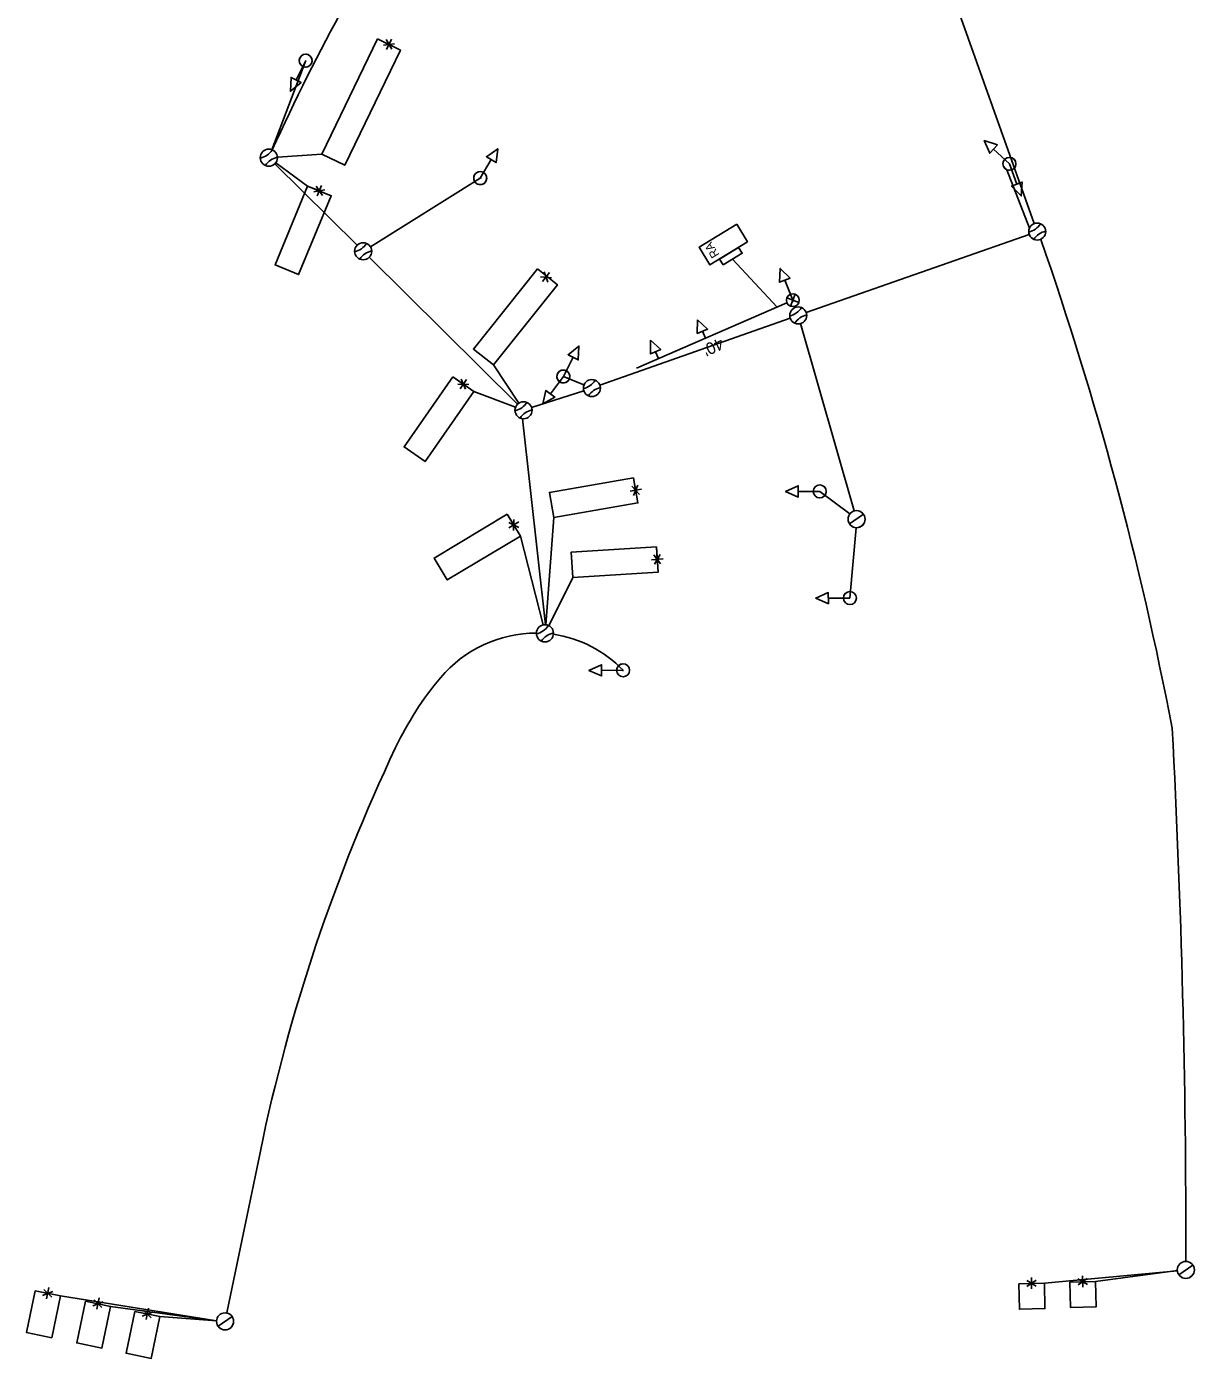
# Model space of a CAD drawing. Extents: x 596176 to 605330, y 332416 to 402398.
# Drawn here: x 602306.3 to 602580, y 356809.5 to 357121.7 of the extents above; entities that cross this region are included whole.
import ezdxf

# ---------------------------------------------------------------- set-up
doc = ezdxf.new("R2010")
doc.units = 0
for name, color, linetype in [('P_LTG', 7, 'Continuous'), ('P_SIG', 7, 'Continuous'), ('P_SIG_Bold', 7, 'Continuous'), ('P_SIG_Conduit', 7, 'Continuous'), ('P_SIG_Loops', 7, 'Continuous')]:
    doc.layers.add(name, color=color, linetype=linetype)

# ---------------------------------------------------------------- blocks, each defined once
blk = doc.blocks.new('_U319')
at = {"layer": 'P_SIG'}
for p, q in [((-0.68, 0.11), (-0.74, 0.13)), ((-0.72, 0.06), (-0.74, 0.13)), ((-0.02, -0.02), (-0.44, -0.02))]:
    blk.add_line(p, q, dxfattribs=at)
for centre, radius, start, end in [((-0.48, 0.45), 0.392, 205.2667, 239.91514), ((-0.38, 0.36), 0.462, 189.31535, 221.17149), ((-0.41, 0.42), 0.442, 221.4708, 266.03474)]:
    blk.add_arc(centre, radius, start, end, dxfattribs=at)

msp = doc.modelspace()

# ---------------------------------------------------------------- linework, layer by layer
at = {"layer": 'P_SIG'}
for p, q in [((602369.5, 357109.17), (602371.75, 357113.7)), ((602532.98, 357092.96), (602536.69, 357089.52)), ((602415.26, 357090.49), (602412.65, 357086.16)), ((602538.45, 357084.77), (602536.7, 357089.51)), ((602482.25, 357055.94), (602471.82, 357067.19)), ((602484.06, 357062.24), (602485.93, 357057.54)), ((602464.75, 357050.26), (602465.45, 357048.63)), ((602453.75, 357045.47), (602454.45, 357043.84)), ((602434.45, 357044.16), (602432.14, 357039.66)), ((602429.11, 357035.61), (602432.14, 357039.66)), ((602487.18, 357012.73), (602492.24, 357012.73)), ((602499.21, 357005.09), (602502.51, 357007.35)), ((602494.26, 356987.71), (602499.31, 356987.71)), ((602441.1, 356970.78), (602446.15, 356970.79)), ((602576.39, 356829.12), (602579.69, 356831.38)), ((602351.2, 356817.05), (602354.5, 356819.31))]:
    msp.add_line(p, q, dxfattribs=at)
for points in [[(602368.19, 357106.51), (602368.32, 357109.75), (602370.69, 357108.58), (602368.19, 357106.51)], [(602368.32, 357109.75), (602368.19, 357106.51), (602370.69, 357108.58), (602368.32, 357109.75)], [(602530.8, 357094.97), (602533.87, 357093.93), (602532.08, 357091.99), (602530.8, 357094.97)], [(602530.8, 357094.97), (602533.87, 357093.93), (602532.08, 357091.99), (602530.8, 357094.97)], [(602533.87, 357093.93), (602530.8, 357094.97), (602532.08, 357091.99), (602533.87, 357093.93)], [(602416.78, 357093.03), (602416.39, 357089.82), (602414.13, 357091.17), (602416.78, 357093.03)], [(602416.39, 357089.82), (602416.78, 357093.03), (602414.13, 357091.17), (602416.39, 357089.82)], [(602539.48, 357081.99), (602537.22, 357084.31), (602539.69, 357085.23), (602539.48, 357081.99)], [(602537.22, 357084.31), (602539.48, 357081.99), (602539.69, 357085.23), (602537.22, 357084.31)], [(602482.97, 357064.99), (602485.29, 357062.73), (602482.84, 357061.75), (602482.97, 357064.99)], [(602482.97, 357064.99), (602485.29, 357062.73), (602482.84, 357061.75), (602482.97, 357064.99)], [(602485.29, 357062.73), (602482.97, 357064.99), (602482.84, 357061.75), (602485.29, 357062.73)], [(602435.79, 357046.8), (602435.62, 357043.56), (602433.27, 357044.76), (602435.79, 357046.8)], [(602435.62, 357043.56), (602435.79, 357046.8), (602433.27, 357044.76), (602435.62, 357043.56)], [(602427.35, 357033.23), (602428.06, 357036.39), (602430.17, 357034.82), (602427.35, 357033.23)], [(602428.06, 357036.39), (602427.35, 357033.23), (602430.17, 357034.82), (602428.06, 357036.39)], [(602484.22, 357012.72), (602487.18, 357014.04), (602487.19, 357011.41), (602484.22, 357012.72)], [(602487.18, 357014.04), (602484.22, 357012.72), (602487.19, 357011.41), (602487.18, 357014.04)], [(602502.51, 357007.35), (602499.21, 357005.09)], [(602491.3, 356987.7), (602494.25, 356989.02), (602494.26, 356986.39), (602491.3, 356987.7)], [(602494.25, 356989.02), (602491.3, 356987.7), (602494.26, 356986.39), (602494.25, 356989.02)], [(602438.14, 356970.77), (602441.09, 356972.1), (602441.1, 356969.46), (602438.14, 356970.77)], [(602441.09, 356972.1), (602438.14, 356970.77), (602441.1, 356969.46), (602441.09, 356972.1)], [(602579.69, 356831.38), (602576.39, 356829.12)], [(602354.5, 356819.31), (602351.2, 356817.05)]]:
    msp.add_lwpolyline(points, dxfattribs=at)
for points in [[(602472.78, 357075.35), (602463.96, 357069.94), (602466.48, 357065.83), (602475.3, 357071.24)], [(602469.57, 357065.81), (602468.73, 357067.17), (602473.23, 357069.93), (602474.07, 357068.56)], [(602463.58, 357052.97), (602465.96, 357050.78), (602463.54, 357049.74)], [(602452.57, 357048.18), (602454.96, 357045.99), (602452.54, 357044.94)]]:
    msp.add_lwpolyline(points, close=True, dxfattribs=at)
for centre, radius in [((602371.75, 357113.7), 1.52), ((602371.75, 357113.7), 1.52), ((602371.75, 357113.7), 1.52), ((602363.11, 357090.95), 2), ((602536.7, 357089.51), 1.52), ((602536.7, 357089.51), 1.52), ((602536.7, 357089.51), 1.52), ((602412.65, 357086.16), 1.52), ((602412.65, 357086.16), 1.52), ((602412.65, 357086.16), 1.52), ((602543.21, 357073.63), 2), ((602385.23, 357069.01), 2), ((602487.2, 357053.97), 2), ((602432.14, 357039.66), 1.52), ((602432.14, 357039.66), 1.52), ((602432.14, 357039.66), 1.52), ((602432.14, 357039.66), 1.52), ((602432.14, 357039.66), 1.52), ((602432.14, 357039.66), 1.52), ((602438.83, 357036.95), 2), ((602422.81, 357031.74), 2), ((602492.24, 357012.73), 1.52), ((602492.24, 357012.73), 1.52), ((602492.24, 357012.73), 1.52), ((602500.86, 357006.22), 2), ((602499.31, 356987.71), 1.52), ((602499.31, 356987.71), 1.52), ((602499.31, 356987.71), 1.52), ((602427.83, 356979.46), 2), ((602446.15, 356970.79), 1.52), ((602446.15, 356970.79), 1.52), ((602446.15, 356970.79), 1.52), ((602578.04, 356830.25), 2), ((602352.85, 356818.18), 2)]:
    msp.add_circle(centre, radius, dxfattribs=at)
for centre, radius, start, end in [((602371.75, 357113.7), 1.52, 63.7061, 243.7061), ((602371.75, 357113.7), 1.52, 243.7061, 63.7061), ((602360.19, 357095.1), 4.36, 282.2572, 328.1103), ((602365.97, 357086.76), 4.36, 101.3562, 147.2093), ((602536.7, 357089.51), 1.52, 110.3847, 290.3847), ((602536.7, 357089.51), 1.52, 290.3847, 110.3847), ((602412.65, 357086.16), 1.52, 59.1253, 239.1253), ((602412.65, 357086.16), 1.52, 239.1253, 59.1253), ((602540.29, 357077.77), 4.36, 282.2572, 328.1103), ((602546.06, 357069.44), 4.36, 101.3562, 147.2093), ((602382.31, 357073.16), 4.36, 282.2572, 328.1103), ((602388.09, 357064.82), 4.36, 101.3562, 147.2093), ((602484.28, 357058.12), 4.36, 282.2572, 328.1103), ((602490.06, 357049.78), 4.36, 101.3562, 147.2093), ((602432.14, 357039.66), 1.52, 53.3587, 233.3587), ((602432.14, 357039.66), 1.52, 63.0248, 243.0248), ((602432.14, 357039.66), 1.52, 233.3587, 53.3587), ((602432.14, 357039.66), 1.52, 243.0248, 63.0248), ((602435.91, 357041.09), 4.36, 282.2572, 328.1103), ((602441.69, 357032.76), 4.36, 101.3562, 147.2093), ((602419.89, 357035.89), 4.36, 282.2572, 328.1103), ((602425.67, 357027.55), 4.36, 101.3562, 147.2093), ((602492.24, 357012.73), 1.52, 0.1787, 180.1787), ((602492.24, 357012.73), 1.52, 180.1787, 0.1787), ((602500.86, 357006.22), 2, 214.3829, 304.6821), ((602500.86, 357006.22), 2, 304.6821, 34.3829), ((602499.31, 356987.71), 1.52, 0.1787, 180.1787), ((602499.31, 356987.71), 1.52, 180.1787, 0.1787), ((602424.91, 356983.6), 4.36, 282.2572, 328.1103), ((602430.69, 356975.27), 4.36, 101.3562, 147.2093), ((602446.15, 356970.79), 1.52, 0.1787, 180.1787), ((602446.15, 356970.79), 1.52, 180.1787, 0.1787), ((602578.04, 356830.25), 2, 304.6821, 34.3829), ((602578.04, 356830.25), 2, 214.3829, 304.6821), ((602352.85, 356818.18), 2, 304.6821, 34.3829), ((602352.85, 356818.18), 2, 214.3829, 304.6821)]:
    msp.add_arc(centre, radius, start, end, dxfattribs=at)
at = {"layer": 'P_SIG_Bold'}
for p, q in [((602484.53, 357058.09), (602487.32, 357056.99)), ((602486.48, 357058.94), (602485.38, 357056.15)), ((602449.25, 357041.58), (602484.55, 357056.94))]:
    msp.add_line(p, q, dxfattribs=at)
msp.add_circle((602485.93, 357057.54), 1.5, dxfattribs=at)
at = {"layer": 'P_SIG_Conduit'}
for p, q in [((602363.83, 357092.82), (602371.75, 357113.7)), ((602364.53, 357089.54), (602383.81, 357070.42)), ((602386.93, 357070.07), (602412.65, 357086.16)), ((602541.39, 357074.46), (602536.06, 357088.14)), ((602386.65, 357067.6), (602421.39, 357033.15)), ((602486.53, 357055.86), (602486.43, 357056.13)), ((602436.98, 357037.7), (602432.14, 357039.66)), ((602499.31, 356987.71), (602500.77, 357004.22))]:
    msp.add_line(p, q, dxfattribs=at)
for points in [[(602524.96, 357124.65), (602542.53, 357075.51)], [(602489.09, 357054.64), (602541.32, 357072.96)], [(602440.72, 357037.61), (602485.31, 357053.31)], [(602500.31, 357008.14), (602487.75, 357052.05)], [(602424.71, 357032.36), (602436.93, 357036.33)], [(602427.94, 356981.46), (602422.53, 357029.76)], [(602499.26, 357007.43), (602492.24, 357012.73)], [(602361.13, 356858.1), (602353.26, 356820.14)]]:
    msp.add_lwpolyline(points, dxfattribs=at)
for centre, radius, start, end in [((602786.9, 356902.02), 464, 151.0197, 155.7252), ((601778.36, 356804.45), 811, 10.85868, 19.24809), ((602425.88, 356950.04), 29.48, 90.0864, 139.8604), ((602425.74, 356951.37), 28.17, 43.5756, 81.6852), ((602461.52, 356920.15), 76, 139.9541, 154.6474), ((600278.02, 356835.81), 2300.03, 359.91139, 3.02617), ((602772.39, 356772.85), 420, 154.6474, 168.2896)]:
    msp.add_arc(centre, radius, start, end, dxfattribs=at)
at = {"layer": 'P_SIG_Loops'}
for p, q in [((602391.27, 357117.5), (602388.57, 357118.8)), ((602389.97, 357117.31), (602392.54, 357117.65)), ((602390.59, 357118.62), (602391.93, 357116.41)), ((602391.85, 357118.74), (602390.68, 357116.33)), ((602364.73, 357089.77), (602372.2, 357084.31)), ((602375.54, 357091.78), (602365.11, 357091.08)), ((602374.97, 357083.17), (602372.2, 357084.31)), ((602373.68, 357082.91), (602376.24, 357083.4)), ((602374.23, 357084.25), (602375.7, 357082.12)), ((602375.48, 357084.44), (602374.46, 357081.97)), ((602428.92, 357064.03), (602427.27, 357061.93)), ((602427.66, 357064.19), (602428.5, 357061.74)), ((602426.78, 357063.04), (602429.37, 357062.82)), ((602415.8, 357042.4), (602421.72, 357033.42)), ((602408.7, 357037.84), (602406.24, 357039.55)), ((602409.47, 357038.97), (602407.94, 357036.78)), ((602408.21, 357039.06), (602409.18, 357036.66)), ((602407.38, 357037.86), (602409.99, 357037.79)), ((602420.94, 357032.45), (602411.16, 357036.12)), ((602448.18, 357013.92), (602449.97, 357012.03)), ((602449.09, 357012.97), (602448.58, 357015.93)), ((602449.61, 357014.19), (602448.6, 357011.8)), ((602450.44, 357013.23), (602447.8, 357012.77)), ((602420.52, 357004.85), (602418.98, 357007.42)), ((602419.33, 357005.4), (602421.68, 357004.28)), ((602421.69, 357005.57), (602419.4, 357004.19)), ((602420.57, 357006.16), (602420.49, 357003.57)), ((602428.02, 356981.45), (602429.9, 357006.59)), ((602427.39, 356981.41), (602422.07, 357002.27)), ((602454.15, 356996.78), (602453.96, 356999.77)), ((602455.52, 356996.88), (602452.84, 356996.72)), ((602453.35, 356997.82), (602454.91, 356995.75)), ((602454.8, 356997.93), (602453.53, 356995.67)), ((602434.38, 356992.53), (602428.73, 356981.25)), ((602544.88, 356827.16), (602576.05, 356830.06)), ((602576.05, 356830.09), (602556.88, 356827.55)), ((602541.88, 356827.08), (602538.88, 356827.01)), ((602540.76, 356827.78), (602542.97, 356826.42)), ((602540.81, 356826.33), (602542.95, 356827.81)), ((602541.83, 356828.46), (602541.9, 356825.78)), ((602553.88, 356827.47), (602550.88, 356827.4)), ((602552.75, 356828.17), (602554.96, 356826.81)), ((602552.8, 356826.71), (602554.94, 356828.2)), ((602553.82, 356828.85), (602553.89, 356826.17)), ((602310.1, 356824.25), (602312.51, 356825.21)), ((602310.38, 356825.68), (602312.22, 356823.86)), ((602311.58, 356826.09), (602311.03, 356823.47)), ((602314.25, 356824.14), (602350.86, 356818.28)), ((602323.33, 356823.66), (602322.79, 356821.03)), ((602321.85, 356821.81), (602324.27, 356822.77)), ((602322.14, 356823.24), (602323.98, 356821.42)), ((602350.86, 356818.28), (602326.01, 356821.7)), ((602333.42, 356819.41), (602335.83, 356820.37)), ((602333.7, 356820.84), (602335.54, 356819.02)), ((602334.9, 356821.25), (602334.35, 356818.63)), ((602350.86, 356818.28), (602337.57, 356819.3))]:
    msp.add_line(p, q, dxfattribs=at)
for points in [[(602388.57, 357118.8), (602375.52, 357091.79), (602380.92, 357089.18), (602393.97, 357116.19)], [(602372.2, 357084.31), (602364.56, 357065.83), (602370.1, 357063.54), (602377.75, 357082.02)], [(602426.05, 357064.86), (602411.08, 357046.1), (602415.8, 357042.4), (602430.77, 357061.15)], [(602406.24, 357039.55), (602394.81, 357023.14), (602399.73, 357019.71), (602411.16, 357036.12)], [(602448.58, 357015.93), (602428.87, 357012.5), (602429.9, 357006.59), (602449.61, 357010.02)], [(602418.98, 357007.42), (602401.84, 356997.11), (602404.93, 356991.97), (602422.07, 357002.27)], [(602453.96, 356999.77), (602434, 356998.52), (602434.38, 356992.53), (602454.34, 356993.79)], [(602538.88, 356827.01), (602539.03, 356821.01), (602545.02, 356821.16), (602544.88, 356827.16)], [(602550.88, 356827.4), (602551.02, 356821.4), (602557.02, 356821.55), (602556.88, 356827.55)], [(602308.38, 356825.35), (602306.35, 356815.56), (602312.22, 356814.34), (602314.25, 356824.14)], [(602320.13, 356822.92), (602318.1, 356813.13), (602323.98, 356811.91), (602326.01, 356821.7)], [(602331.7, 356820.52), (602329.67, 356810.72), (602335.54, 356809.51), (602337.57, 356819.3)]]:
    msp.add_lwpolyline(points, close=True, dxfattribs=at)

# ---------------------------------------------------------------- block references
at = {"layer": 'P_LTG', "xscale": 0.32808333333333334}
for p, yscale, rotation in [((602412.64, 357086.15), 0.32808333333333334, 28.70662747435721), ((602412.64, 357086.15), 0.3280833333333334, -151.17706427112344), ((602485.93, 357057.53), 0.3280833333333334, -66.35204459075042), ((602485.93, 357057.53), 0.3280833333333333, 113.53164715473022), ((602446.25, 356970.73), 0.3280833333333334, 5.316747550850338)]:
    msp.add_blockref('_U319', p, dxfattribs=dict(at, yscale=yscale, rotation=rotation))

# ---------------------------------------------------------------- texts
at = {"layer": 'P_SIG'}
msp.add_text('RA', height=2, rotation=121.4904, dxfattribs=at).set_placement((602468.77, 357068.19))
at = {"layer": 'P_SIG_Bold'}
msp.add_text("40'", height=2.8, rotation=204.2642, dxfattribs=at).set_placement((602468.97, 357048.87))

doc.saveas('drawing.dxf')
